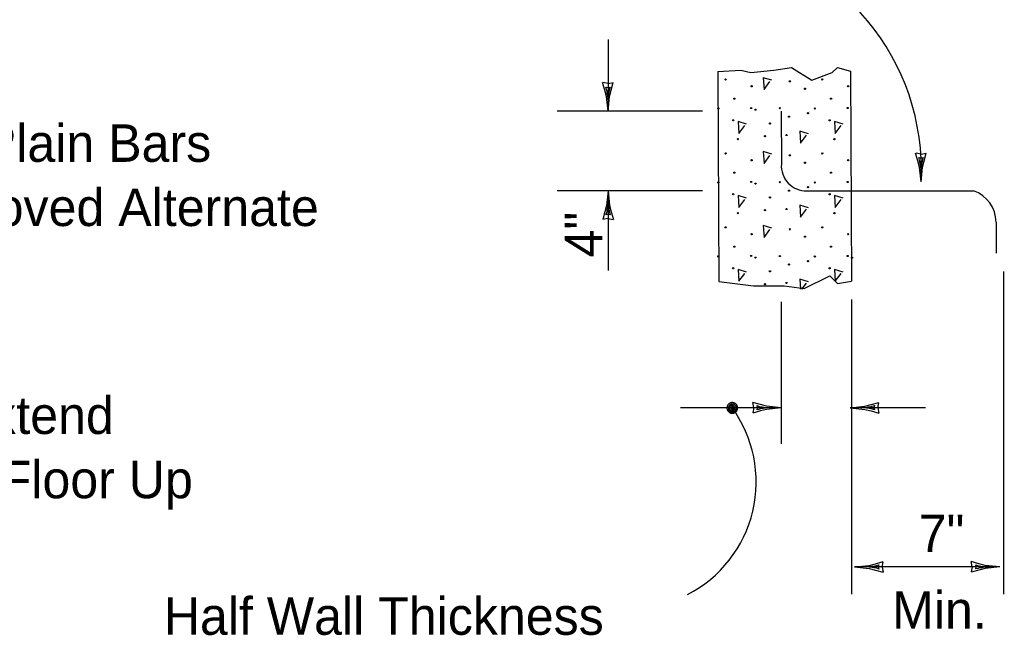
# Model space of a CAD drawing. Extents: x -7.1 to 10, y -5 to 6.
# Drawn here: x 4.208 to 5.944, y 2.54 to 3.626 of the extents above; entities that cross this region are included whole.
import ezdxf

# ---------------------------------------------------------------- set-up
doc = ezdxf.new("R2010")
doc.units = 0
for name, color, linetype in [('Level 4', 7, 'Continuous'), ('Level 5', 7, 'Continuous'), ('Level 6', 7, 'Continuous'), ('Level 7', 7, 'Continuous')]:
    doc.layers.add(name, color=color, linetype=linetype)

msp = doc.modelspace()

# ---------------------------------------------------------------- linework, layer by layer
at = {"layer": 'Level 4'}
for p, q in [((5.4402, 3.5348), (5.4417, 3.1641)), ((5.6741, 3.5357), (5.6756, 3.165)), ((5.5518, 3.4649), (5.5521, 3.3715)), ((5.5971, 3.3242), (5.8914, 3.3242)), ((5.9311, 3.2691), (5.9313, 3.2142))]:
    msp.add_line(p, q, dxfattribs=at)
for points in [[(5.4402, 3.5348), (5.4806, 3.5374), (5.4985, 3.5329), (5.5388, 3.5374), (5.5702, 3.5418), (5.6061, 3.5194), (5.6419, 3.5329), (5.6509, 3.5418), (5.6741, 3.5357)], [(5.4417, 3.1641), (5.503, 3.1564), (5.5568, 3.1564), (5.5926, 3.1519), (5.6374, 3.1743), (5.6509, 3.1609), (5.6756, 3.165)]]:
    msp.add_lwpolyline(points, dxfattribs=at)
for centre, radius, start, end in [((5.5961, 3.3683), 0.0441, 175.842, 271.1948), ((5.871, 3.2676), 0.0602, 1.3903, 70.2079)]:
    msp.add_arc(centre, radius, start, end, dxfattribs=at)
at = {"layer": 'Level 5'}
for p, q in [((5.4554, 3.5213), (5.4539, 3.5204)), ((5.4554, 3.5213), (5.4554, 3.5213)), ((5.4994, 3.5089), (5.4994, 3.5076)), ((5.5663, 3.5176), (5.5663, 3.5176)), ((5.5663, 3.5176), (5.5669, 3.5161)), ((5.6257, 3.5213), (5.6243, 3.5204)), ((5.6257, 3.5213), (5.6257, 3.5213)), ((5.6697, 3.5089), (5.6697, 3.5076)), ((5.4697, 3.4879), (5.4701, 3.4865)), ((5.64, 3.4879), (5.6404, 3.4865)), ((5.4405, 3.4693), (5.4405, 3.4693)), ((5.5081, 3.4675), (5.5081, 3.4675)), ((5.6009, 3.4638), (5.6009, 3.4638)), ((5.6108, 3.4693), (5.6108, 3.4693)), ((5.5289, 3.4452), (5.5291, 3.4453)), ((5.4771, 3.4168), (5.4771, 3.4168)), ((5.6474, 3.4168), (5.6474, 3.4168)), ((5.4554, 3.3908), (5.4539, 3.3899)), ((5.4554, 3.3908), (5.4554, 3.3908)), ((5.5663, 3.3871), (5.5663, 3.3871)), ((5.5663, 3.3871), (5.5669, 3.3855)), ((5.6257, 3.3908), (5.6243, 3.3899)), ((5.6257, 3.3908), (5.6257, 3.3908)), ((5.4994, 3.3784), (5.4994, 3.377)), ((5.6697, 3.3784), (5.6697, 3.377)), ((5.4697, 3.3573), (5.4701, 3.356)), ((5.64, 3.3573), (5.6404, 3.356)), ((5.5081, 3.337), (5.5081, 3.337)), ((5.6009, 3.3333), (5.6009, 3.3333)), ((5.6108, 3.3388), (5.6108, 3.3388)), ((5.5289, 3.3147), (5.5291, 3.3147)), ((5.4771, 3.2862), (5.4771, 3.2862)), ((5.6474, 3.2862), (5.6474, 3.2862)), ((5.4554, 3.2602), (5.4539, 3.2594)), ((5.4554, 3.2602), (5.4554, 3.2602)), ((5.4994, 3.2478), (5.4994, 3.2465)), ((5.5663, 3.2565), (5.5663, 3.2565)), ((5.5663, 3.2565), (5.5669, 3.255)), ((5.6257, 3.2602), (5.6243, 3.2594)), ((5.6257, 3.2602), (5.6257, 3.2602)), ((5.6697, 3.2478), (5.6697, 3.2465)), ((5.4697, 3.2268), (5.4701, 3.2254)), ((5.64, 3.2268), (5.6404, 3.2254)), ((5.5081, 3.2065), (5.5081, 3.2065)), ((5.6009, 3.2028), (5.6009, 3.2028)), ((5.6108, 3.2082), (5.6108, 3.2082)), ((5.5289, 3.1841), (5.5291, 3.1842)), ((5.5999, 3.1636), (5.5847, 3.1682)), ((5.5847, 3.1682), (5.5857, 3.1507)), ((5.5883, 3.1504), (5.5964, 3.1612))]:
    msp.add_line(p, q, dxfattribs=at)
for points in [[(5.5355, 3.5193), (5.5203, 3.5239), (5.5215, 3.503), (5.532, 3.5169)], [(5.4909, 3.442), (5.4757, 3.4466), (5.4769, 3.4257), (5.4874, 3.4397)], [(5.6612, 3.442), (5.6461, 3.4466), (5.6473, 3.4257), (5.6577, 3.4397)], [(5.5999, 3.4247), (5.5847, 3.4293), (5.5859, 3.4083), (5.5964, 3.4223)], [(5.5355, 3.3887), (5.5203, 3.3934), (5.5215, 3.3724), (5.532, 3.3864)], [(5.4909, 3.3114), (5.4757, 3.3161), (5.4769, 3.2951), (5.4874, 3.3091)], [(5.6612, 3.3114), (5.6461, 3.3161), (5.6473, 3.2951), (5.6577, 3.3091)], [(5.5999, 3.2941), (5.5847, 3.2988), (5.5859, 3.2778), (5.5964, 3.2918)], [(5.5355, 3.2582), (5.5203, 3.2629), (5.5215, 3.2419), (5.532, 3.2559)], [(5.4909, 3.1809), (5.4757, 3.1856), (5.4769, 3.1646), (5.4874, 3.1786)], [(5.6612, 3.1809), (5.6461, 3.1856), (5.6473, 3.1646), (5.6577, 3.1786)]]:
    msp.add_lwpolyline(points, dxfattribs=at)
for centre in [(5.4536, 3.5207), (5.4996, 3.5088), (5.5672, 3.5175), (5.624, 3.5207), (5.67, 3.5088), (5.5938, 3.5044), (5.4692, 3.4868), (5.4988, 3.4704), (5.6396, 3.4868), (5.6691, 3.4704), (5.4408, 3.4696), (5.5064, 3.4674), (5.5494, 3.4701), (5.5655, 3.4551), (5.5991, 3.4613), (5.6111, 3.4696), (5.4671, 3.4487), (5.5321, 3.4431), (5.6374, 3.4487), (5.5233, 3.4206), (5.5611, 3.4227), (5.4754, 3.4154), (5.6457, 3.4154), (5.4536, 3.3902), (5.5672, 3.387), (5.624, 3.3902), (5.4996, 3.3782), (5.5938, 3.3738), (5.67, 3.3782), (5.4692, 3.3563), (5.6396, 3.3563), (5.4408, 3.339), (5.4988, 3.3399), (5.5064, 3.3369), (5.5494, 3.3396), (5.6111, 3.339), (5.6691, 3.3399), (5.4671, 3.3182), (5.5655, 3.3246), (5.5991, 3.3307), (5.6374, 3.3182), (5.5321, 3.3126), (5.4754, 3.2848), (5.5233, 3.2901), (5.5611, 3.2921), (5.6457, 3.2848), (5.4536, 3.2597), (5.4996, 3.2477), (5.5672, 3.2565), (5.624, 3.2597), (5.67, 3.2477), (5.5938, 3.2433), (5.4692, 3.2257), (5.6396, 3.2257), (5.4408, 3.2085), (5.4988, 3.2093), (5.5064, 3.2063), (5.5494, 3.2091), (5.5655, 3.1941), (5.5991, 3.2002), (5.6111, 3.2085), (5.6691, 3.2093), (5.6767, 3.2063), (5.4671, 3.1876), (5.5321, 3.1821), (5.6374, 3.1876), (5.5233, 3.1595), (5.5611, 3.1616)]:
    msp.add_circle(centre, 0.00105, dxfattribs=at)
at = {"layer": 'Level 7'}
for p, q in [((5.2463, 3.5915), (5.2463, 3.4649)), ((5.2465, 3.5135), (5.2374, 3.5153)), ((5.2465, 3.5135), (5.2556, 3.5153)), ((5.4128, 3.4649), (5.1566, 3.4649)), ((5.7987, 3.3889), (5.7897, 3.3907)), ((5.7987, 3.3889), (5.8079, 3.3907)), ((5.4128, 3.3242), (5.1566, 3.3242)), ((5.2463, 3.3242), (5.2463, 3.1839)), ((5.2461, 3.2756), (5.237, 3.2738)), ((5.2461, 3.2756), (5.2552, 3.2738)), ((5.9438, 3.1821), (5.9438, 2.6126)), ((5.5519, 3.1281), (5.5519, 2.878)), ((5.6756, 3.1327), (5.6756, 2.6126)), ((5.5034, 2.9416), (5.5016, 2.9507)), ((5.5519, 2.9414), (5.3741, 2.9414)), ((5.5034, 2.9416), (5.5016, 2.9326)), ((5.8063, 2.9414), (5.6737, 2.9414)), ((5.7222, 2.9412), (5.7241, 2.9503)), ((5.7222, 2.9412), (5.7241, 2.9321)), ((5.9376, 2.6605), (5.6814, 2.6605)), ((5.7299, 2.6603), (5.7318, 2.6694)), ((5.7299, 2.6603), (5.7318, 2.6512)), ((5.889, 2.6607), (5.8872, 2.6698)), ((5.889, 2.6607), (5.8872, 2.6516))]:
    msp.add_line(p, q, dxfattribs=at)
for points in [[(5.2463, 3.4649), (5.2435, 3.4908), (5.2408, 3.5017), (5.2368, 3.5153)], [(5.2463, 3.4855), (5.2457, 3.4924), (5.2449, 3.4967), (5.2445, 3.5003), (5.2437, 3.5032), (5.2426, 3.5074), (5.2463, 3.5066), (5.2501, 3.5074), (5.2487, 3.504), (5.2481, 3.5013), (5.2477, 3.4985), (5.2471, 3.4959), (5.2469, 3.4934), (5.2465, 3.4906), (5.2463, 3.4855)], [(5.2463, 3.4649), (5.2491, 3.4908), (5.2518, 3.5017), (5.2556, 3.5153)], [(5.7986, 3.3403), (5.7957, 3.3662), (5.7931, 3.3771), (5.789, 3.3907)], [(5.7986, 3.3403), (5.8014, 3.3662), (5.804, 3.3771), (5.8079, 3.3907)], [(5.7986, 3.3609), (5.798, 3.3678), (5.7971, 3.3721), (5.7967, 3.3757), (5.7959, 3.3786), (5.7949, 3.3828), (5.7986, 3.382), (5.8024, 3.3828), (5.801, 3.3794), (5.8004, 3.3768), (5.8, 3.3739), (5.7994, 3.3713), (5.7992, 3.3688), (5.7988, 3.366), (5.7986, 3.3609)], [(5.2463, 3.3242), (5.2435, 3.2983), (5.2408, 3.2874), (5.237, 3.2738)], [(5.2463, 3.3242), (5.2491, 3.2983), (5.2518, 3.2874), (5.2558, 3.2738)], [(5.2463, 3.3036), (5.2469, 3.2967), (5.2477, 3.2924), (5.2481, 3.2888), (5.2489, 3.2859), (5.25, 3.2817), (5.2463, 3.2825), (5.2424, 3.2817), (5.2439, 3.2851), (5.2445, 3.2878), (5.2449, 3.2906), (5.2455, 3.2932), (5.2457, 3.2957), (5.2461, 3.2985), (5.2463, 3.3036)], [(5.5519, 2.9414), (5.526, 2.9442), (5.5151, 2.9469), (5.5016, 2.9507)], [(5.6737, 2.9414), (5.6996, 2.9443), (5.7105, 2.9469), (5.7241, 2.9509)], [(5.5519, 2.9414), (5.526, 2.9386), (5.5151, 2.936), (5.5015, 2.9319)], [(5.5313, 2.9414), (5.5244, 2.9408), (5.5202, 2.94), (5.5165, 2.9396), (5.5137, 2.9388), (5.5094, 2.9378), (5.5102, 2.9414), (5.5094, 2.9453), (5.5129, 2.9439), (5.5155, 2.9433), (5.5183, 2.9429), (5.521, 2.9423), (5.5234, 2.9421), (5.5263, 2.9416), (5.5313, 2.9414)], [(5.6737, 2.9414), (5.6996, 2.9386), (5.7105, 2.936), (5.7241, 2.9321)], [(5.6943, 2.9414), (5.7012, 2.942), (5.7054, 2.9429), (5.7091, 2.9433), (5.7119, 2.9441), (5.7162, 2.9451), (5.7154, 2.9414), (5.7162, 2.9376), (5.7127, 2.939), (5.7101, 2.9396), (5.7073, 2.94), (5.7046, 2.9406), (5.7022, 2.9408), (5.6993, 2.9412), (5.6943, 2.9414)], [(5.6814, 2.6605), (5.7073, 2.6633), (5.7182, 2.666), (5.7318, 2.67)], [(5.6814, 2.6605), (5.7073, 2.6577), (5.7182, 2.655), (5.7318, 2.6512)], [(5.702, 2.6605), (5.7089, 2.6611), (5.7132, 2.6619), (5.7168, 2.6623), (5.7196, 2.6632), (5.7239, 2.6642), (5.7231, 2.6605), (5.7239, 2.6567), (5.7204, 2.6581), (5.7178, 2.6587), (5.715, 2.6591), (5.7124, 2.6597), (5.7099, 2.6599), (5.7071, 2.6603), (5.702, 2.6605)], [(5.9376, 2.6605), (5.9117, 2.6633), (5.9008, 2.666), (5.8872, 2.6698)], [(5.9376, 2.6605), (5.9117, 2.6577), (5.9008, 2.655), (5.8872, 2.651)], [(5.917, 2.6605), (5.9101, 2.6599), (5.9058, 2.6591), (5.9022, 2.6587), (5.8993, 2.6579), (5.8951, 2.6569), (5.8959, 2.6605), (5.8951, 2.6644), (5.8985, 2.6629), (5.9012, 2.6623), (5.904, 2.6619), (5.9066, 2.6613), (5.9091, 2.6611), (5.9119, 2.6607), (5.917, 2.6605)]]:
    msp.add_lwpolyline(points, dxfattribs=at)
for points in [[(5.461, 2.9493), (5.4603, 2.9489), (5.4596, 2.9484), (5.459, 2.9479), (5.4584, 2.9473), (5.4579, 2.9467), (5.4575, 2.946), (5.4571, 2.9453), (5.4567, 2.9445), (5.4565, 2.9437), (5.4563, 2.9429), (5.4561, 2.9421), (5.4561, 2.9413), (5.4561, 2.9405), (5.4562, 2.9396), (5.4564, 2.9388), (5.4566, 2.9381), (5.4569, 2.9373), (5.4572, 2.9365), (5.4577, 2.9358), (5.4582, 2.9352), (5.4587, 2.9346), (5.4593, 2.934), (5.4599, 2.9335), (5.4606, 2.933), (5.4613, 2.9326), (5.4621, 2.9323), (5.4629, 2.932), (5.4637, 2.9318), (5.4645, 2.9317), (5.4653, 2.9316), (5.4661, 2.9316), (5.4669, 2.9317), (5.4678, 2.9319), (5.4685, 2.9321), (5.4693, 2.9324), (5.47, 2.9328), (5.4708, 2.9332), (5.4714, 2.9337), (5.472, 2.9342), (5.4726, 2.9348), (5.4731, 2.9355), (5.4736, 2.9361), (5.474, 2.9369), (5.4743, 2.9376), (5.4746, 2.9384), (5.4748, 2.9392), (5.4749, 2.94), (5.475, 2.9408), (5.4749, 2.9417), (5.4749, 2.9425), (5.4747, 2.9433), (5.4745, 2.9441), (5.4742, 2.9448), (5.4738, 2.9456), (5.4734, 2.9463), (5.4729, 2.9469), (5.4724, 2.9476), (5.4718, 2.9481), (5.4711, 2.9487), (5.4704, 2.9491), (5.4697, 2.9495), (5.469, 2.9498), (5.4682, 2.9501), (5.4674, 2.9503), (5.4666, 2.9504), (5.4658, 2.9505), (5.4649, 2.9505), (5.4641, 2.9504), (5.4633, 2.9502), (5.4625, 2.95), (5.4618, 2.9497)], [(5.4623, 2.947), (5.4618, 2.9466), (5.4613, 2.9463), (5.4608, 2.9459), (5.4604, 2.9454), (5.46, 2.9449), (5.4597, 2.9444), (5.4594, 2.9439), (5.4591, 2.9433), (5.4589, 2.9428), (5.4588, 2.9421), (5.4587, 2.9415), (5.4586, 2.9409), (5.4586, 2.9403), (5.4587, 2.9397), (5.4588, 2.9391), (5.459, 2.9385), (5.4592, 2.9379), (5.4595, 2.9374), (5.4598, 2.9368), (5.4602, 2.9363), (5.4606, 2.9359), (5.461, 2.9354), (5.4615, 2.9351), (5.462, 2.9347), (5.4626, 2.9344), (5.4631, 2.9342), (5.4637, 2.934), (5.4643, 2.9338), (5.4649, 2.9337), (5.4655, 2.9337), (5.4661, 2.9337), (5.4668, 2.9338), (5.4674, 2.9339), (5.468, 2.934), (5.4685, 2.9343), (5.4691, 2.9345), (5.4696, 2.9349), (5.4701, 2.9352), (5.4706, 2.9356), (5.471, 2.9361), (5.4714, 2.9366), (5.4717, 2.9371), (5.472, 2.9376), (5.4723, 2.9382), (5.4725, 2.9388), (5.4726, 2.9394), (5.4727, 2.94), (5.4728, 2.9406), (5.4728, 2.9412), (5.4727, 2.9418), (5.4726, 2.9424), (5.4724, 2.943), (5.4722, 2.9436), (5.4719, 2.9441), (5.4716, 2.9447), (5.4712, 2.9452), (5.4708, 2.9456), (5.4704, 2.9461), (5.4699, 2.9464), (5.4694, 2.9468), (5.4688, 2.9471), (5.4683, 2.9473), (5.4677, 2.9475), (5.4671, 2.9477), (5.4665, 2.9478), (5.4659, 2.9478), (5.4653, 2.9478), (5.4646, 2.9478), (5.464, 2.9476), (5.4634, 2.9475), (5.4629, 2.9472)], [(5.4631, 2.9447), (5.4628, 2.9445), (5.4624, 2.9443), (5.4621, 2.944), (5.4618, 2.9437), (5.4616, 2.9434), (5.4614, 2.943), (5.4612, 2.9427), (5.461, 2.9423), (5.4609, 2.9419), (5.4608, 2.9415), (5.4607, 2.9411), (5.4607, 2.9407), (5.4607, 2.9403), (5.4607, 2.9399), (5.4608, 2.9395), (5.4609, 2.9391), (5.4611, 2.9387), (5.4612, 2.9383), (5.4615, 2.938), (5.4617, 2.9376), (5.462, 2.9373), (5.4623, 2.937), (5.4626, 2.9368), (5.4629, 2.9366), (5.4633, 2.9364), (5.4637, 2.9362), (5.4641, 2.9361), (5.4645, 2.936), (5.4649, 2.9359), (5.4653, 2.9359), (5.4657, 2.9359), (5.4661, 2.9359), (5.4665, 2.936), (5.4669, 2.9361), (5.4673, 2.9363), (5.4676, 2.9364), (5.468, 2.9367), (5.4683, 2.9369), (5.4686, 2.9372), (5.4689, 2.9375), (5.4692, 2.9378), (5.4694, 2.9381), (5.4696, 2.9385), (5.4698, 2.9389), (5.4699, 2.9393), (5.47, 2.9396), (5.4701, 2.9401), (5.4701, 2.9405), (5.4701, 2.9409), (5.4701, 2.9413), (5.47, 2.9417), (5.4699, 2.9421), (5.4697, 2.9425), (5.4695, 2.9428), (5.4693, 2.9432), (5.4691, 2.9435), (5.4688, 2.9438), (5.4685, 2.9441), (5.4682, 2.9444), (5.4678, 2.9446), (5.4675, 2.9448), (5.4671, 2.945), (5.4667, 2.9451), (5.4663, 2.9452), (5.4659, 2.9453), (5.4655, 2.9453), (5.4651, 2.9453), (5.4647, 2.9452), (5.4643, 2.9452), (5.4639, 2.9451), (5.4635, 2.9449)], [(5.4646, 2.9428), (5.4644, 2.9427), (5.4642, 2.9426), (5.4641, 2.9425), (5.4639, 2.9423), (5.4638, 2.9421), (5.4637, 2.942), (5.4636, 2.9418), (5.4635, 2.9416), (5.4634, 2.9414), (5.4634, 2.9412), (5.4634, 2.941), (5.4633, 2.9408), (5.4633, 2.9406), (5.4634, 2.9404), (5.4634, 2.9402), (5.4635, 2.94), (5.4635, 2.9398), (5.4636, 2.9396), (5.4637, 2.9394), (5.4639, 2.9393), (5.464, 2.9391), (5.4641, 2.939), (5.4643, 2.9389), (5.4645, 2.9387), (5.4646, 2.9386), (5.4648, 2.9386), (5.465, 2.9385), (5.4652, 2.9384), (5.4654, 2.9384), (5.4656, 2.9384), (5.4658, 2.9384), (5.4661, 2.9384), (5.4663, 2.9385), (5.4664, 2.9385), (5.4666, 2.9386), (5.4668, 2.9387), (5.467, 2.9388), (5.4672, 2.9389), (5.4673, 2.939), (5.4675, 2.9392), (5.4676, 2.9394), (5.4677, 2.9395), (5.4678, 2.9397), (5.4679, 2.9399), (5.468, 2.9401), (5.468, 2.9403), (5.468, 2.9405), (5.4681, 2.9407), (5.4681, 2.9409), (5.468, 2.9411), (5.468, 2.9413), (5.4679, 2.9415), (5.4679, 2.9417), (5.4678, 2.9419), (5.4677, 2.9421), (5.4675, 2.9422), (5.4674, 2.9424), (5.4673, 2.9425), (5.4671, 2.9426), (5.4669, 2.9428), (5.4667, 2.9429), (5.4666, 2.9429), (5.4664, 2.943), (5.4662, 2.9431), (5.466, 2.9431), (5.4658, 2.9431), (5.4656, 2.9431), (5.4653, 2.9431), (5.4651, 2.943), (5.4649, 2.943), (5.4648, 2.9429)]]:
    msp.add_lwpolyline(points, close=True, dxfattribs=at)
for centre, radius, start, end in [((5.3888, 3.3617), 0.4103, 357.0056, 82.5558), ((5.2842, 2.8104), 0.2235, 297.2142, 36.1639)]:
    msp.add_arc(centre, radius, start, end, dxfattribs=at)

# ---------------------------------------------------------------- texts
at = {"layer": 'Level 6'}
for s, height, p in [('1" Dia. Plain Bars', 0.066125, (3.8562, 3.3754)), ('Or Approved Alternate', 0.066125, (3.8562, 3.2621)), ('Ladder Shall Extend', 0.066125, (3.5779, 2.8951)), ("From 2' Above Floor Up", 0.066125, (3.5779, 2.7817)), ('7"', 0.06613, (5.7945, 2.6866)), ('Min.', 0.06613, (5.7475, 2.5514)), ('Half Wall Thickness', 0.066125, (4.4624, 2.5407))]:
    msp.add_text(s, height=height, dxfattribs=at).set_placement(p)
msp.add_text('4"', height=0.06613, rotation=90, dxfattribs=at).set_placement((5.2362, 3.2067))

doc.saveas('drawing.dxf')
